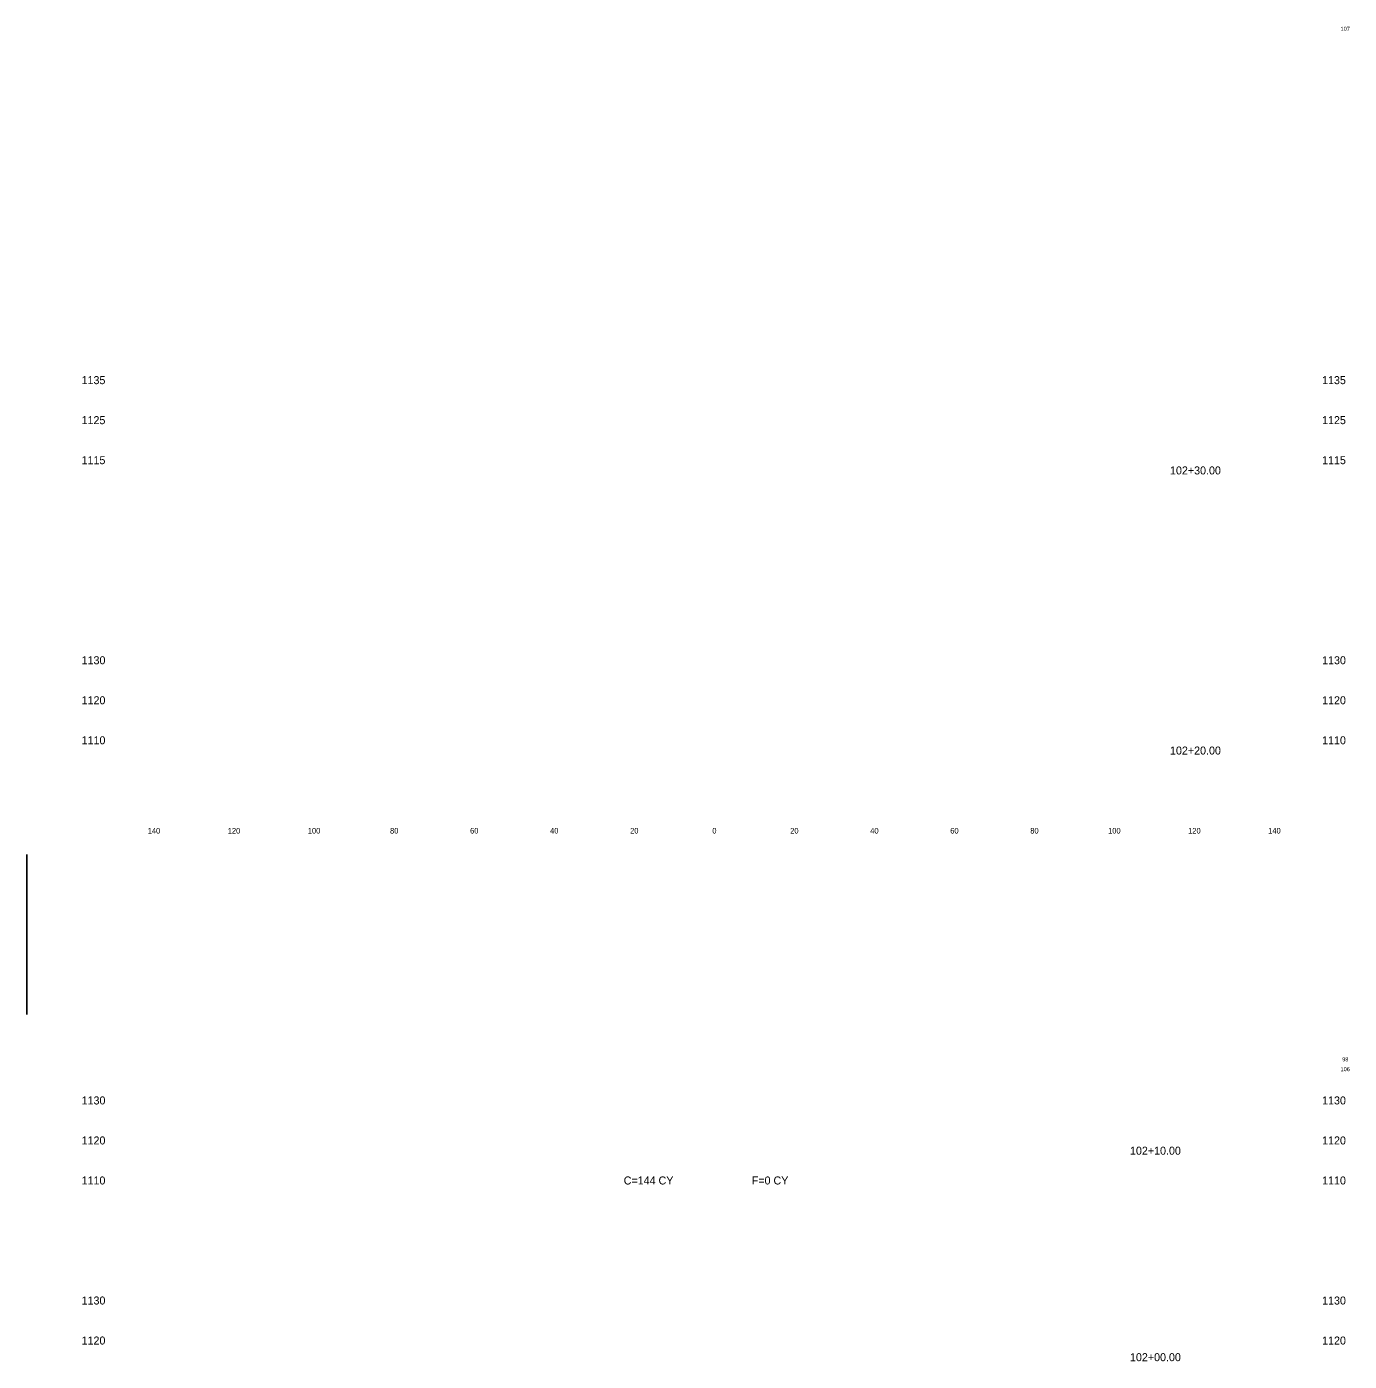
# Model space of a CAD drawing. Extents: x -200 to 1319, y -200 to 2499.
# Drawn here: x 988 to 1318.5, y 2165.8 to 2499.3 of the extents above; entities that cross this region are included whole.
import ezdxf

# ---------------------------------------------------------------- set-up
doc = ezdxf.new("R2010")
doc.units = 0
for name, color, linetype in [('Default', 7, 'Continuous'), ('DESIGN - SHEET - Corner Text', 7, 'Continuous'), ('DESIGN - TYPICAL - Text', 7, 'Continuous'), ('SURVEY - CENTERLINE - Preliminary', 7, 'Continuous')]:
    doc.layers.add(name, color=color, linetype=linetype)

msp = doc.modelspace()

# ---------------------------------------------------------------- linework, layer by layer
at = {"layer": 'SURVEY - CENTERLINE - Preliminary'}
msp.add_line((988, 2252.5), (988, 2292.5), dxfattribs=at)

# ---------------------------------------------------------------- texts
at = {"layer": 'Default'}
for s, height, p in [('     1135     ', 2, (998, 2410)), ('     1135     ', 2, (1308, 2410)), ('     1125     ', 2, (998, 2400)), ('     1125     ', 2, (1308, 2400)), ('     1115     ', 2, (998, 2390)), ('     1115     ', 2, (1308, 2390)), ('     102+30.00     ', 2, (1270, 2387.44)), ('     1130     ', 2, (998.01, 2340)), ('     1130     ', 2, (1308.01, 2340)), ('     1120     ', 2, (998.01, 2330)), ('     1120     ', 2, (1308.01, 2330)), ('     1110     ', 2, (998.01, 2320)), ('     1110     ', 2, (1308.01, 2320)), ('     102+20.00     ', 2, (1270, 2317.44)), ('     140     ', 1.4, (1015.65, 2297.7)), ('     120     ', 1.4, (1035.65, 2297.7)), ('     100     ', 1.4, (1055.65, 2297.7)), ('     80     ', 1.4, (1076.2, 2297.7)), ('     60     ', 1.4, (1096.2, 2297.7)), ('     40     ', 1.4, (1116.2, 2297.7)), ('     20     ', 1.4, (1136.2, 2297.7)), ('     0     ', 1.4, (1156.74, 2297.7)), ('     20     ', 1.4, (1176.2, 2297.7)), ('     40     ', 1.4, (1196.2, 2297.7)), ('     60     ', 1.4, (1216.2, 2297.7)), ('     80     ', 1.4, (1236.2, 2297.7)), ('     100     ', 1.4, (1255.65, 2297.7)), ('     120     ', 1.4, (1275.65, 2297.7)), ('     140     ', 1.4, (1295.65, 2297.7)), ('     1130     ', 2, (998.01, 2230)), ('     1130     ', 2, (1308.01, 2230)), ('     1120     ', 2, (998.01, 2220)), ('     1120     ', 2, (1308.01, 2220)), ('     102+10.00     ', 2, (1260, 2217.44)), ('     1110     ', 2, (998.01, 2210)), ('     1110     ', 2, (1308.01, 2210)), ('     1130     ', 2, (998.01, 2180)), ('     1130     ', 2, (1308.01, 2180)), ('     1120     ', 2, (998.01, 2170)), ('     1120     ', 2, (1308.01, 2170)), ('     102+00.00     ', 2, (1260, 2165.84))]:
    msp.add_text(s, height=height, dxfattribs=at).set_placement(p)
at = {"layer": 'DESIGN - SHEET - Corner Text'}
for s, p in [('107', (1316.35, 2498.31)), ('98', (1316.75, 2240.75)), ('106', (1316.35, 2238.31))]:
    msp.add_text(s, height=1, dxfattribs=at).set_placement(p)
at = {"layer": 'DESIGN - TYPICAL - Text'}
for s, p in [('C=144 CY', (1137.2, 2210)), ('F=0 CY', (1169.2, 2210))]:
    msp.add_text(s, height=2, dxfattribs=at).set_placement(p)

doc.saveas('drawing.dxf')
